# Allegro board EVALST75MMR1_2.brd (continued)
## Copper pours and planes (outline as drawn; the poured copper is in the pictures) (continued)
VDDIO on TOP: 58.57,15.7 62.59,15.7 62.59,16.41 62.28,16.41 61.62,17.07 61.62,18.24 60.05,18.24 59.89,18.08 59.89,17.63 59.64,17.37 58.78,17.37 58.32,17.83 58.32,18.39 57.61,18.39 57.15,17.93 57.15,17.12
VDDIO on TOP: 73.81,40.84 75.95,40.84 76.1,40.69 76.1,39.98 76.33,39.75 77.72,39.75 78.66,38.81 79.32,38.81 80.24,39.73 86.31,39.73 86.92,39.12 86.92,36.58 86.21,35.86 78.79,35.86 76.71,37.95 76.1,37.95 76.05,38 76.05,38.61 75.59,39.07 75.18,39.07 74.32,39.93 73.81,39.93
VDDIO on TOP: 60.96,33.73 61.87,33.73 62.03,33.88 62.89,33.88 62.89,33.02 63.75,32.16 63.75,30.99 63.6,30.84 61.47,32.97 60.96,32.97
VDDIO on TOP: 32.21,18.75 32.21,17.53 33.17,16.56 33.17,15.9 34.54,15.9 34.54,16.87 35.05,17.37 35.05,18.19 34.49,18.75
VDDIO on TOP: 32.16,29.01 33.68,27.48 35.15,27.48 35.81,28.14 37.34,28.14 41.1,24.38 47.14,24.38 47.14,25.2 45.92,26.42 41.25,26.42 37.39,30.28 33.93,30.28 32.82,31.39 32.46,31.39 32.16,31.09
VDDIO on TOP: 52.88,29.26 52.88,21.74 51.46,23.16 51.46,30.07 51.66,30.28 53.54,30.28 53.54,29.46 53.44,29.36 52.98,29.36
VDDIO on TOP: 19.05,21.59 17.78,21.59 17.14,20.95 17.14,15.88 14.48,13.21 12.57,13.21 12.57,10.54 13.46,9.65 18.54,9.65 18.8,9.91 18.8,20.83 18.92,20.95 19.43,20.95 19.43,21.21
VDDIO on BOTTOM: 51.77,23.88 55.47,23.88 55.68,23.67 55.68,23.37 55.47,23.16 53.34,23.16 52.58,22.4 52.58,19.3 52.32,19.05 52.02,19.05 51.46,19.61 51.46,23.57
VDDIO on BOTTOM: 80.11,52.48 83.97,48.62 83.97,45.52 79.6,41.15 79.6,36.63 80.06,36.17 84.28,36.17 86.92,38.81 86.92,48.59 81.57,53.94
L on TOP: 14.94,58.01 14.27,58.01 13.77,57.51 13.77,54.66 11.94,52.83 11.94,52.48 14.33,50.09 14.33,43.79 14.83,43.28 18.24,43.28 18.8,43.84 18.8,50.6 15.7,53.7 15.7,57.25
L on BOTTOM: 14.83,43.28 18.24,43.28 18.8,43.84 18.8,44.75 18.41,45.14 14.88,45.14 14.33,44.58 14.33,43.79
N on TOP: 20.64,58.03 20.64,54.85 20.83,54.66 22.71,54.66 23.05,55 23.05,58.28 20.89,58.28
PA_OUT on TOP: 67.01,36.42 66.09,35.51 66.09,34.34 66.29,34.14 68.94,34.14 69.04,34.24 69.04,37.08 67.77,38.35 67.01,38.35
PRI on TOP: 37.13,56.64 37.13,51.36 42.32,46.18 45.87,46.18 46.08,46.38 46.08,47.9 45.72,48.26 42.88,48.26 40.01,51.13 40.01,56.64
N19516233 on TOP: 26.29,58.17 26.29,55.12 27.69,53.72 27.69,48.51 32.82,43.38 38,43.38 38.4,43.79 38.4,44.45 31.75,51.1 31.75,56.77 30.35,58.17
N19516233 on BOTTOM: 32.82,43.38 38,43.38 38.4,43.79 38.4,44.45 37.82,45.03 32.87,45.03 32.41,44.58 32.41,43.79
N19717143 on TOP: 31.19,6.2 31.19,0.89 42.82,0.89 42.82,7.82 42.72,7.92 41.76,7.92 41.2,7.37 41.2,6.45 40.79,6.05 39.52,6.05 38.86,5.38 34.59,5.38 33.78,6.2
N19754951 on TOP: 71.42,57.76 71.42,56.49 72.34,55.58 75.03,55.58 75.23,55.37 75.23,53.59 76.61,53.59 76.61,56.08 74.63,58.06 71.73,58.06
N19754973 on TOP: 81.17,54.34 79.71,52.88 78.49,54.1 78.49,54.97 79.15,55.63 79.88,55.63
N19754973 on BOTTOM: 66.8,58.04 67.82,58.04 68.71,57.15 68.71,56.52 69.23,55.99 79.51,55.99 81.17,54.34 79.71,52.88 79.12,53.47 68,53.47 66.04,55.42 66.04,57.28

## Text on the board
BOTTOM: 02 - LATO SALDATURE
Board Geometry/Soldermask Bottom: 05 - SOLDER MASK BOTTOM
Package Geometry/Pastemask Bottom: EVALST7580r1_R2 PASTE MASK LS
Ref Des/Silkscreen Bottom: 04 - SERIGRAFIA LS
TOP: 01 - LATO COMPONENTI
Ref Des/Assembly Top: 07 - PIANO DI MONTAGGIO TOP
Board Geometry/Soldermask Top: 04 - SOLDER MASK TOP
Package Geometry/Pastemask Top: 06 - PASTE MASK LC
Ref Des/Silkscreen Top: PA_OUT | GND | ZC_IN | RX_IN | TX | OUT | ST75MM | ACIN | STM32 | CL | SW1 | 3V3 | VCC | EVALST75MM Rev1.2 | 03 - SERIGRAFIA LC
PAGE_OUTLINE: IFARCAD | 02-08-2017 | EVALST75MMR12 | 1.2 | EVALST75MM
DIMENSION: FABRICATION NOTE
User.30: FIGURE | SIZE | 12.0 | 35.0 | 40.0 | 44.0 | 51.0 | 60.0 | 128.0 | DRILL CHART: TOP to BOTTOM | ALL UNITS ARE IN MILS | PLATED | NON-PLATED | QTY | 193 | 44 | 40 | 16 | 8 | 1 | 4
User.32: PIANO DI MONTAGGIO LATO COMPONENTI
